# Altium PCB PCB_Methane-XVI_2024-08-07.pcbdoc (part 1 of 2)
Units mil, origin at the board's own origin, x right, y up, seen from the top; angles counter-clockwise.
Board outline 4553.3 x 5155.85 mil, 2 copper layers (Top Layer, Bottom Layer); 67 components, 58 nets, 315 pads, 114 vias.
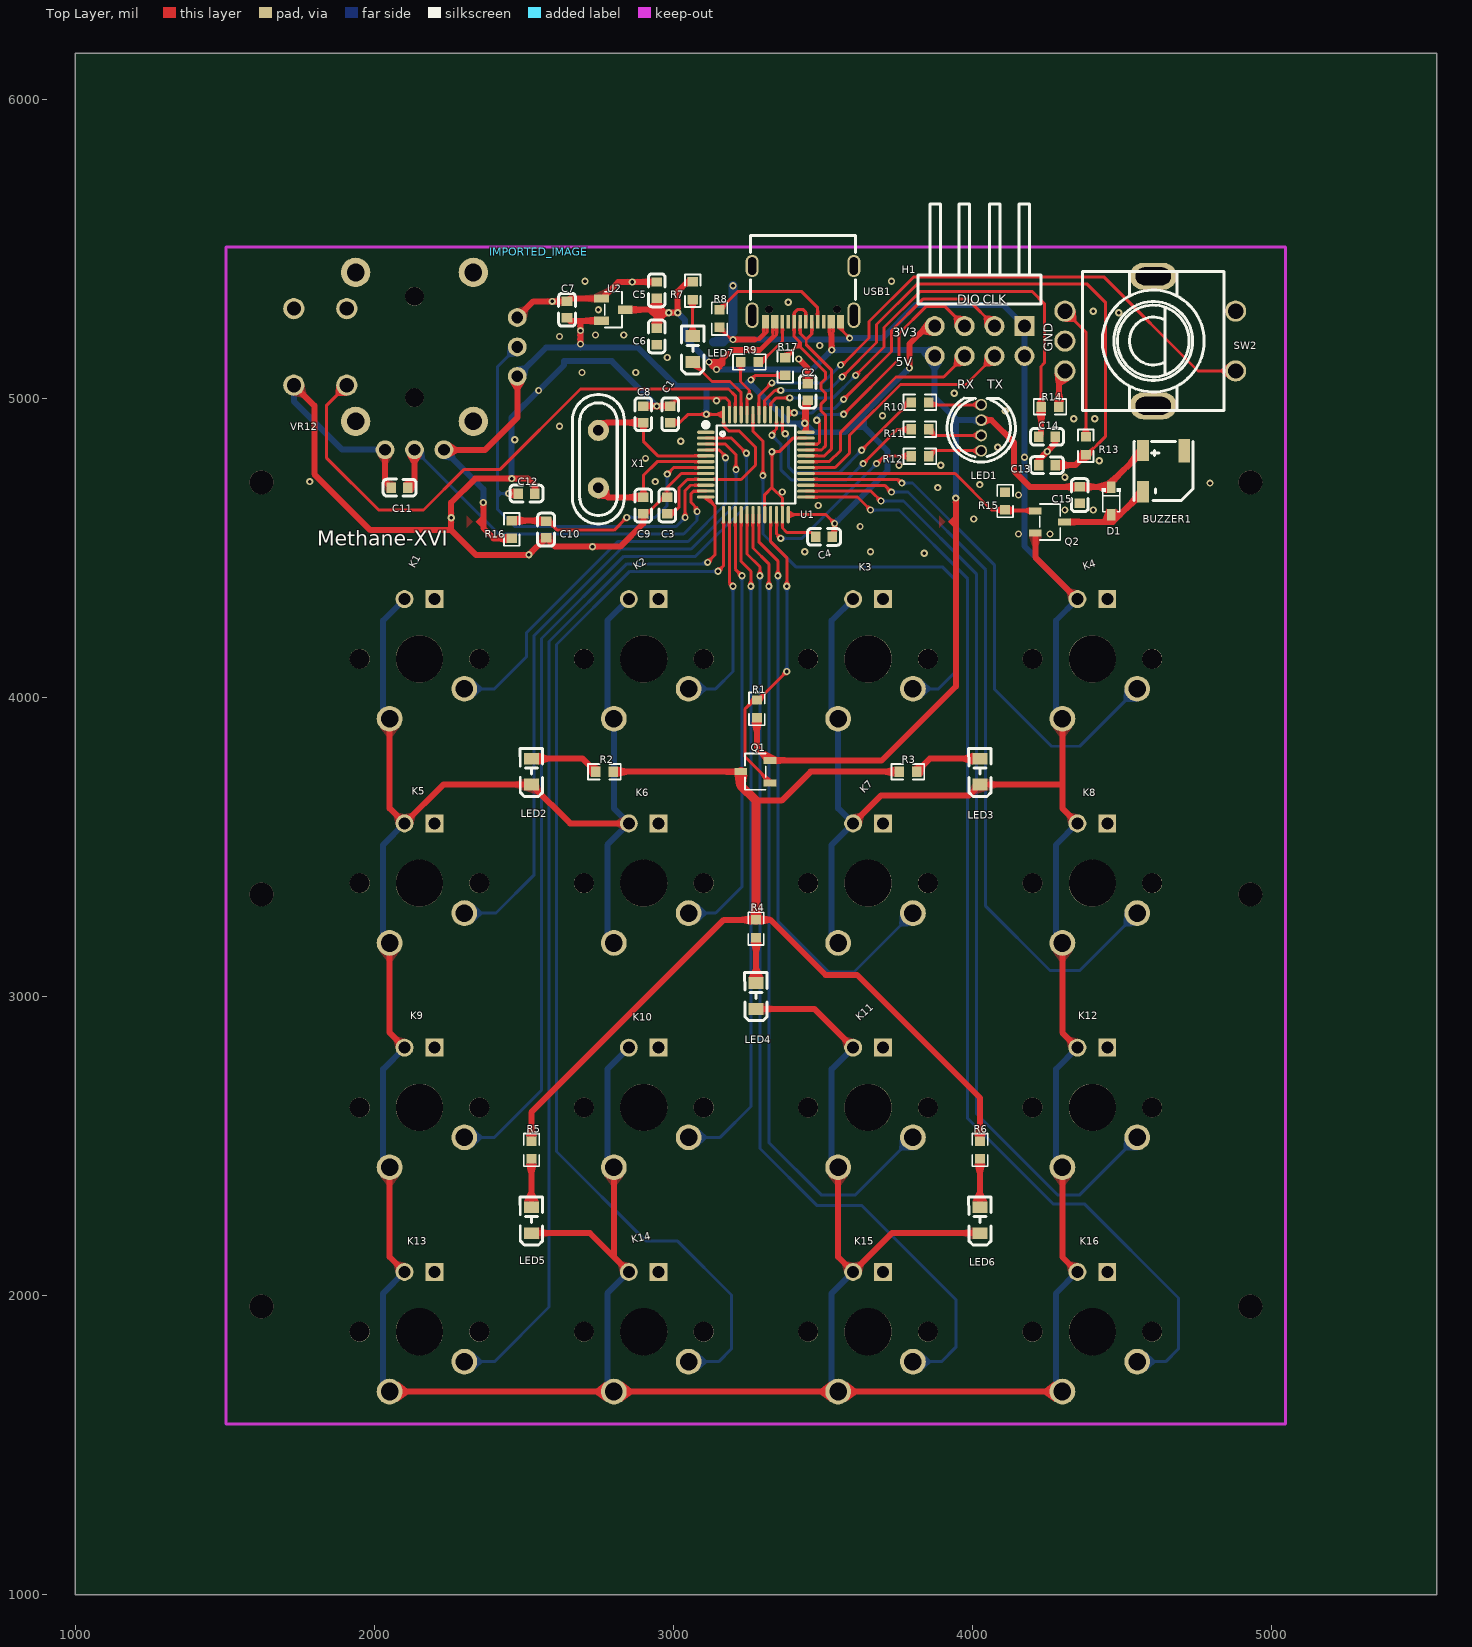
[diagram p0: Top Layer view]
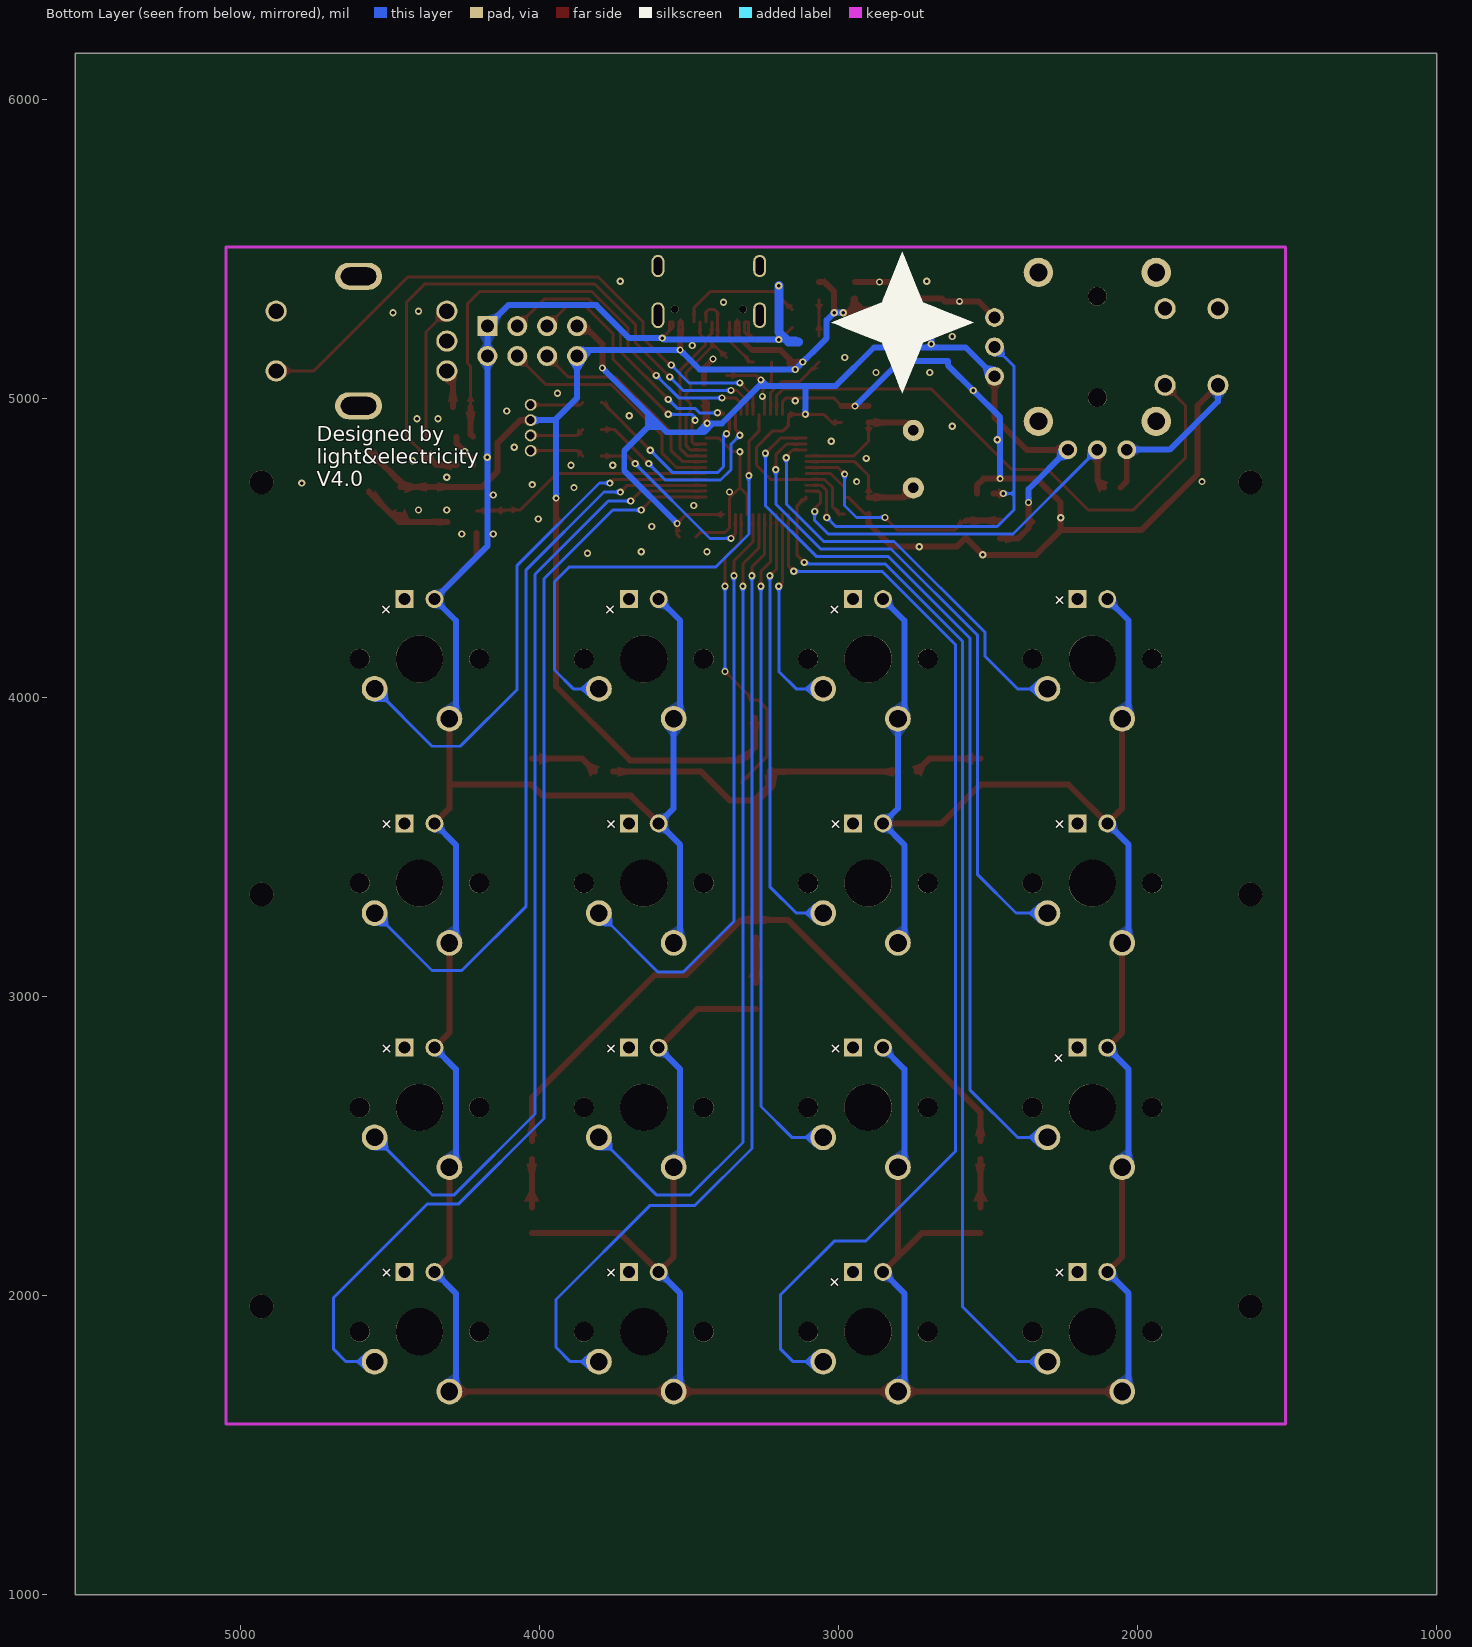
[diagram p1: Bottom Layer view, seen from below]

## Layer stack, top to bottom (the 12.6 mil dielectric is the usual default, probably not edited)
Top Layer: signal copper (thickness not stored)
Dielectric: dielectric 12.6, FR-4, Dk 4.8
Bottom Layer: signal copper (thickness not stored)

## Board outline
5553.3,1000 1000,1000 1000,6155.85 5553.3,6155.85

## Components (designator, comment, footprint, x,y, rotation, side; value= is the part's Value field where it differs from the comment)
BUZZER1 "FST-5020" BUZ-SMD_FST-5020 4640,4757.94 r270 top
C1 "0.1u" C0603 2990,4947.94 r270 top
C2 "0.1u" C0603 3450,5022.94 r270 top
C3 "0.1u" C0603 2980,4642.94 r270 top
C4 "0.1u" C0603 3505,4537.94 r0 top
C5 "0.1u" C0603 2945,5362.94 r90 top
C6 "1u" C0603 2945,5207.94 r270 top
C7 "1u" C0603 2645,5297.94 r90 top
C8 "22p" C0603 2900,4947.94 r270 top
C9 "22p" C0603 2900,4642.94 r90 top
C10 "0.1u" C0603 2575,4562.94 r90 top
C11 "1nF" C0603 2085,4702.94 r180 top
C12 "1nF" C0603 2510,4682.94 r0 top
C13 "0.1u" C0603 4250,4777.94 r0 top
C14 "0.1u" C0603 4250,4872.94 r180 top
C15 "0.1u" C0603 4360,4677.94 r90 top
D1 "B5819WS" SOD-323_L1.8-W1.3-LS2.5-RD 4465,4657.94 r270 top
H1 "PZ254-2-04-W-8.5" HDR-TH_8P-P2.54-H-M-R2-C4-S2.54-N 4024.68,5192.98 r180 top
IMPORTED_IMAGE "IMPORTED_IMAGE" IMPORTED_IMAGE 2550.47,5491.19 r0 top
K1 "NUM1" NEIL_MX_1U 2151.65,4130 r0 top
K2 "NUM2" NEIL_MX_1U 2901.65,4130 r0 top
K3 "NUM3" NEIL_MX_1U 3651.65,4130 r0 top
K4 "KEYA" NEIL_MX_1U 4401.65,4130 r0 top
K5 "NUM4" NEIL_MX_1U 2151.65,3380 r0 top
K6 "NUM5" NEIL_MX_1U 2901.65,3380 r0 top
K7 "NUM6" NEIL_MX_1U 3651.65,3380 r0 top
K8 "KEYB" NEIL_MX_1U 4401.65,3380 r0 top
K9 "NUM7" NEIL_MX_1U 2151.65,2630 r0 top
K10 "NUM8" NEIL_MX_1U 2901.65,2630 r0 top
K11 "NUM9" NEIL_MX_1U 3651.65,2630 r0 top
K12 "KEYC" NEIL_MX_1U 4401.65,2630 r0 top
K13 "KEY+" NEIL_MX_1U 2151.65,1880 r0 top
K14 "NUM0" NEIL_MX_1U 2901.65,1880 r0 top
K15 "KEY+" NEIL_MX_1U 3651.65,1880 r0 top
K16 "KEYD" NEIL_MX_1U 4401.65,1880 r0 top
LED1 "φ5 RGB Transparent" LED-TH_4P-BD5.8-P1.30 4030,4902.94 r90 top
LED2 "0805" LED0805-RD_GREEN 2526,3752.94 r90 top
LED3 "0805" LED0805-RD_GREEN 4026,3752.94 r90 top
LED4 "0805" LED0805-RD_GREEN 3277,3002.94 r90 top
LED5 "0805" LED0805-RD_GREEN 2526,2252.94 r90 top
LED6 "0805" LED0805-RD_GREEN 4026,2252.94 r90 top
LED7 "0805" LED0805-RD_GREEN 3065.39,5166.09 r90 top
Q1 "IRLML6401" SOT-23-3_L2.9-W1.6-P1.90-LS2.8-BR 3275.01,3752.94 r0 top
Q2 "AO3400" SOT-23-3_L2.9-W1.6-P1.90-LS2.8-BR 4260,4587.94 r180 top
R1 "10k" R0603 3280,3962.94 r90 top
R2 "220R" R0603 2770,3752.94 r0 top
R3 "220R" R0603 3785,3752.94 r180 top
R4 "220R" R0603 3277,3227.94 r90 top
R5 "220R" R0603 2526,2487.94 r90 top
R6 "220R" R0603 4026,2487.94 r90 top
R7 "1k" R0603 3065.4,5361.04 r90 top
R8 "5.1k" R0603 3155,5267.94 r270 top
R9 "5.1k" R0603 3255,5122.94 r0 top
R10 "220R" R0603 3825,4987.94 r0 top
R11 "220R" R0603 3825,4897.94 r0 top
R12 "220R" R0603 3825,4807.94 r0 top
R13 "3.3k" R0603 4380,4842.94 r90 top
R14 "3.3k" R0603 4260,4972.94 r180 top
R15 "10k" R0603 4110,4657.94 r270 top
R16 "10k" R0603 2460,4562.94 r270 top
R17 "1.5k" R0603 3375,5107.94 r270 top
SW2 "EC11" SW-TH_5PIN_EC11E15244G1 4595.51,5192.98 r270 top
U1 "STM32F103C6T6" LQFP-48_L7.0-W7.0-P0.50-LS9.0-BL 3276.7,4779.64 r270 top
U2 "662K." SOT-23-3_L2.9-W1.3-P1.90-LS2.4-BR 2800,5297.94 r180 top
USB1 "TYPEC-304YDSW-ACP16" USB-C-SMD_TYPEC-304YDSW-ACP16 3434.13,5350.46 r180 top
VR12 "RKJXV122400R" RKJXV122400R 2134.92,5173.3 r270 top
X1 "8MHz" HC-49S_L11.0-W4.4-P4.88 2750,4797.94 r270 top

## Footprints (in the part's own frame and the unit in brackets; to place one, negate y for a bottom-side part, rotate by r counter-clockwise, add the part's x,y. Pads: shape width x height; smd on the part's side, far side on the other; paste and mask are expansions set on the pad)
BUZ-SMD_FST-5020 [mm]
  rect 1.8x1 smd paste+0 mask+0.051: 1(-1.75,-1.75) 2(1.75,-1.75)
  rect 2x1 smd paste+0 mask+0.051: 3(-1.75,1.75)
  silkscreen extent -2.5,-2.5 2.5,2.5
C0603 [mm]
  rect 0.8x0.9 smd paste+0 mask+0.051: 1(-0.7,0) 2(0.7,0)
  silkscreen extent -1.41,-0.71 1.39,0.72
HC-49S_L11.0-W4.4-P4.88 [mm]
  round 1.8 hole 0.9 paste+0 mask+0.051: 1(-2.44,0) 2(2.44,0)
  silkscreen extent -5.5,-2.2 5.5,2.2
HDR-TH_8P-P2.54-H-M-R2-C4-S2.54-N [mm]
  rect 1.7x1.7 hole 1.1 paste+0 mask+0.05: 1(-3.81,-1.27)
  round 1.7 hole 1.1 paste+0 mask+0.05: 2(-3.81,1.27) 3(-1.27,-1.27) 4(-1.27,1.27) 5(1.27,-1.27) 6(1.27,1.27) 7(3.81,-1.27) 8(3.81,1.27)
  silkscreen extent -5.23,-11.63 5.23,-3.13
IMPORTED_IMAGE [mil]
LED0805-RD_GREEN [mm]
  rect 1x1.25 smd paste+0 mask+0.051: 1(-1.1,0) 2(1.1,0)
  silkscreen extent -2.1,-0.95 1.98,0.96
LED-TH_4P-BD5.8-P1.30 [mm]
  round 1 hole 0.7 paste+0 mask+0.051: 1(1.95,0) 2(0.65,0) 3(-0.65,0) 4(-1.95,0)
  silkscreen extent -2.91,-2.9 2.51,2.9
LQFP-48_L7.0-W7.0-P0.50-LS9.0-BL [mm]
  oval 0.27x1.5 smd paste+0 mask+0.05: 1(-2.75,-4.25) 2(-2.25,-4.25) 3(-1.75,-4.25) 4(-1.25,-4.25) 5(-0.75,-4.25) 6(-0.25,-4.25) 7(0.25,-4.25) 8(0.75,-4.25) 9(1.25,-4.25) 10(1.75,-4.25) 11(2.25,-4.25) 12(2.75,-4.25) 25(2.75,4.25) 26(2.25,4.25) 27(1.75,4.25) 28(1.25,4.25) 29(0.75,4.25) 30(0.25,4.25) 31(-0.25,4.25) 32(-0.75,4.25) 33(-1.25,4.25) 34(-1.75,4.25) 35(-2.25,4.25) 36(-2.75,4.25)
  oval 1.5x0.27 smd paste+0 mask+0.05: 13(4.25,-2.75) 14(4.25,-2.25) 15(4.25,-1.75) 16(4.25,-1.25) 17(4.25,-0.75) 18(4.25,-0.25) 19(4.25,0.25) 20(4.25,0.75) 21(4.25,1.25) 22(4.25,1.75) 23(4.25,2.25) 24(4.25,2.75) 37(-4.25,2.75) 38(-4.25,2.25) 39(-4.25,1.75) 40(-4.25,1.25) 41(-4.25,0.75) 42(-4.25,0.25) 43(-4.25,-0.25) 44(-4.25,-0.75) 45(-4.25,-1.25) 46(-4.25,-1.75) 47(-4.25,-2.25) 48(-4.25,-2.75)
  silkscreen extent -3.59,-4.46 3.3,3.34
NEIL_MX_1U [mil]
  round 86 hole 59 paste+0 mask+4: 1(-100,-200) 2(150,-100)
  rect 60x60 hole 40 paste+0 mask+4: +(50,200)
  round 60 hole 40 paste+0 mask+4: -(-50,200)
  round 66.93 hole 66.93 unplated paste+0: ""(-200,0) ""(200,0)
  round 157.48 hole 157.48 unplated paste+0: ""(0,0)
R0603 [mil]
  rect 31.75x34.02 smd paste-3937.01 mask+2: 1(-29.66,0) 2(29.65,0)
  silkscreen extent -55,-26 55,26
RKJXV122400R [mm]
  round 1.8 hole 1.2 paste+0 mask+0.051: a(-3.25,-5.75) b(-3.25,-10.25) c(3.25,-5.75) d(3.25,-10.25)
  round 1.6 hole 1 paste+0 mask+0.051: A1(2.5,8.73) A2(0,8.73) A3(-2.5,8.73) B1(8.73,-2.5) B2(8.73,0) B3(8.73,2.5)
  round 2.5 hole 1.5 paste+0 mask+0.051: S1(-6.325,5) S1(-6.325,-5) S1(6.325,5) S1(6.325,-5)
  round 1.6 hole 1.6 unplated paste+0: ""(-4.3,0) ""(4.3,0)
SOD-323_L1.8-W1.3-LS2.5-RD [mm]
  rect 1x0.75 smd paste+0 mask+0.051: 1(-1.173,0) 2(1.173,0)
  silkscreen extent -1.08,-0.8 0.9,0.8
SOT-23-3_L2.9-W1.3-P1.90-LS2.4-BR [mm]
  rect 1.25x0.7 smd paste+0 mask+0.051: 1(1,-0.95) 2(1,0.95) 3(-1,0)
  silkscreen extent -0.73,-1.53 0.73,1.53
SOT-23-3_L2.9-W1.6-P1.90-LS2.8-BR [mm]
  rect 1.07x0.6 smd paste+0 mask+0.051: 1(1.235,-0.95) 2(1.235,0.95) 3(-1.235,0)
  silkscreen extent -0.88,-1.54 0.88,1.54
SW-TH_5PIN_EC11E15244G1 [mm]
  oval 2.3x4 hole 1.5 slot 3 at 90 deg paste+0 mask+0.102: 6(5.5,0.25) 7(-5.5,0.25)
  round 1.8 hole 1.3 paste+0 mask+0.102: A(-2.54,-7.25) B(2.54,-7.25) C(0,-7.25) D(-2.54,7.25) E(2.54,7.25)
  silkscreen extent -5.9,-5.75 5.9,6.25
USB-C-SMD_TYPEC-304YDSW-ACP16 [mm]
  oval 1.1x2.2 hole 0.7 slot 1.8 at 90 deg paste+0 mask+0.051: 17(-4.32,1.808) 20(4.32,1.808)
  oval 1.1x1.9 hole 0.7 slot 1.5 at 90 deg paste+0 mask+0.051: 18(-4.32,-2.373) 19(4.32,-2.373)
  rect 0.3x1.15 smd paste-100 mask+0.051: A1(-3.35,2.373) A4(-2.55,2.373) A5(-1.25,2.373) A6(-0.25,2.373) A7(0.25,2.373) A8(1.25,2.373) A9(2.55,2.372) A12(3.35,2.373) B1(3.05,2.373) B4(2.25,2.372) B5(1.75,2.373) B6(0.75,2.373) B7(-0.75,2.373) B8(-1.75,2.373) B9(-2.25,2.373) B12(-3.05,2.373)
  round 0.65 hole 0.65 unplated paste+0: ""(-2.89,1.307) ""(2.89,1.308)
  silkscreen extent -4.47,-4.97 4.47,0.49

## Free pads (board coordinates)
  round 80 hole 80 unplated paste+0: ""(1623.11,1964.64) ""(1623.11,3342.59) ""(1623.11,4720.54) ""(4930.19,1964.64) ""(4930.19,3342.59) ""(4930.19,4720.54)

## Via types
v1: diameter 24.41, hole 12.2, Top Layer to Bottom Layer, tented both sides, 59 vias
v2: diameter 24, hole 12, Top Layer to Bottom Layer, tented both sides, 55 vias

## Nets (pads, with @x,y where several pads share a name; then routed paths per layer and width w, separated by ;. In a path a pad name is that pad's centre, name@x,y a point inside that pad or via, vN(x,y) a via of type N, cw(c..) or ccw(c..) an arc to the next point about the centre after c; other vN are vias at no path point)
3V3: C1.2 C2.2 C3.2 C4.2 C7.1 H1.7 R16.2 R17.2 U1.9 U1.24 U1.36 U1.48 U2.2 VR12.A1 VR12.B3 | length 5096.1
  Top Layer w10: C3.2@2980,4615.34 2997.4,4615.34 3020,4637.94 3020,4702.94 3047.4,4730.34 3109.3,4730.34 3227.4,4730.34 3275,4777.94 3275,4837.94 3220,4892.94 3185,4892.94 3168.4,4909.54 3168.4,4946.94 3168.4,4947.94 v2(3111.01,4947.94) 3050,4947.94 3022.4,4920.34 C1.2@2990,4920.34 ; v2(3260,5062.94) 3275.3,5078.24 R17.2@3375,5078.24 ; U1.24@3384.9,4612.24 3510.7,4612.24 v2(3540,4582.94) 3540,4545.34 C4.2@3532.55,4537.94 ; v2(3440,4917.94) 3444,4913.94 U1.36@3444,4887.84 ; U1.36@3444.02,4887.91 3450,4893.84 C2.2@3450,4995.34
  Top Layer w20: VR12.B3@2233.34,4829.59 2235,4827.94 2370,4827.94 2478.6,4936.54 VR12.A1@2478.6,5074.84 ; v2(2365,4652.94) 2365,4567.94 2399.7,4533.24 R16.2@2460,4533.24 ; C7.1@2645,5270.34 2654.8,5260.54 U2.2@2760.63,5260.54 ; v1(2690,5183.24) v1(2690,5227.94) 2690,5260.54 ; v2(3440,4917.94) 3440,4985.34 C2.2@3450,4995.34 ; v2(3790,5102.94) 3790,5182.94 3850.04,5242.98 H1.7@3874.68,5242.98
  Bottom Layer w20: VR12.B3@2233.34,4829.59 2365,4697.93 v2(2365,4652.94) ; VR12.A1@2478.6,5074.84 2575,5171.24 2881.7,5171.24 3010,5042.94 3265,5042.94 ; v1@2690,5171.24 v1(2690,5183.24) v1(2690,5227.94) ; v2(3111.01,4947.94) 3111.01,5042.94 ; 3197.15,5042.94 3240,5042.94 v2(3260,5062.94) 3260,5047.94 3265,5042.94 ; v2(3540,4582.94) 3716.9,4759.84 3716.9,4826.04 3615,4927.94 ; 3637,4949.94 3637.8,4905.14 ; 3637.35,4905.59 3592.65,4905.59 3575,4887.94 ; v2(3790,5102.94) 3575,4887.94 ; 3265,5042.94 3390,4917.94 ; 3390,4917.94 3420,4917.94 3450,4887.94 3470,4887.94 ; 3390,4917.94 v2(3440,4917.94) 3470,4887.94 ; 3470,4887.94 3575,4887.94
+5V: BUZZER1.1 C5.1 C6.1 C15.2 D1.1 H1.8 LED1.2 Q1.2 R1.1 R7.2 U2.3 USB1.A4 USB1.A9 USB1.B4 USB1.B9 | length 5330.8
  Top Layer w10: 3245.2,5158.14 3290.2,5158.14 3345.6,5213.44 3345.6,5257.04 3333.7,5257.04 3333.7,5211.64 3285,5162.94 3250,5162.94 ; 3522.7,5220.24 3522.7,5257.04 3534.5,5257.04 3534.5,5222.44 3527.5,5215.44 3522.7,5220.24
  Top Layer w20: U2.3@2839.37,5297.94 2938.2,5297.94 2950,5309.74 ; 2917.67,5297.94 2921.96,5297.94 2950,5269.9 ; 2922,5297.94 2945,5320.94 C5.1@2945,5335.34 ; C6.1@2950,5233.04 C5.1@2950,5332.94 ; 2950,5262.74 2975.2,5287.94 v1(2985,5287.94) ; 2950,5309.78 2971.84,5287.94 v1(2985,5287.94) ; R7.2@3065.4,5390.69 3047.8,5390.74 3015,5357.94 v1(3015,5287.94) v1(2985,5287.94) ; 3145,5112.94 3135,5122.94 v1(3120,5122.94) ; R1.1@3280,3933.24 3280,3833.94 Q1.2@3323.62,3790.34 3697.4,3790.34 3945,4037.94 v2(3945,4667.94) ; 3285,5162.94 3195,5162.94 3165,5132.94 ; 3527.5,5215.44 3530,5215.44 v2(3530,5162.94) ; LED1.2@4030,4928.53 4064.4,4928.54 4140,4852.94 4140,4757.94 4192.4,4705.54 C15.2@4360,4705.49 ; D1.1@4465,4704.1 4463.6,4705.54 C15.2@4360,4705.49 ; BUZZER1.1@4571.1,4826.84 4449.8,4705.54 C15.2@4360,4705.49 ; v1(3120,5122.94) v2(3145,5097.94) 3165,5117.94 3165,5132.94 ; v1(3120,5122.94) 3155,5122.94 3165,5132.94
  Bottom Layer w20: v1(2985,5287.94) v1(3015,5287.94) 3040.3,5262.64 3040.3,5202.64 v2(3145,5097.94) 3465,5097.94 v2(3530,5162.94) 3874.7,5162.94 H1.8@3874.7,5142.94 ; H1.8@3874.68,5142.98 3874.68,5003.26 3949.41,4928.53 ; v2(3945,4667.94) 3945,4924.12 3949.41,4928.53 ; LED1.2@4030,4928.53 3949.41,4928.53
ANA1: C11.1 U1.11 VR12.B2 | length 1367.3
  Top Layer w10: v2(3080,4622.94) 3080,4632.94 3060,4652.94 3060,4682.94 3068.1,4691.04 U1.11@3109.3,4691.04
  Top Layer w20: C11.1@2112.55,4702.94 2134.9,4725.34 VR12.B2@2134.92,4829.59
  Bottom Layer w10: VR12.B2@2134.92,4829.59 2416.6,4547.94 3035,4547.94 3080,4592.94 v2(3080,4622.94)
ANA2: C12.1 U1.10 VR12.A2 | length 1497.3
  Top Layer w10: v2(3040,4602.94) 3040,4692.94 3057.8,4710.74 U1.10@3109.3,4710.74
  Top Layer w20: v1(2450,4682.94) C12.1@2482.45,4682.94
  Bottom Layer w10: 2413.1,4672.94 2423.1,4682.94 ; 2413.1,4702.57 2413.1,4692.94 2423.1,4682.94 ; v1(2450,4682.94) 2423.1,4682.94 ; VR12.A2@2478.6,5173.24 2413.1,5107.74 2413.1,4629.84 2470,4572.94 3010,4572.94 v2(3040,4602.94)
BUZZ: Q2.1 R15.2 U1.29 | length 894.2
  Top Layer w10: U1.29@3444,4750.04 3942.9,4750.04 4064.7,4628.24 R15.2@4110,4628.24 ; R15.2@4114.7,4627.94 4194.7,4627.94 Q2.1@4197.3,4625.34 ; R15.2@4117.3,4625.34 Q2.1@4211.38,4625.34
BUZZER1_2: BUZZER1.2 D1.2 Q2.3 | length 608.8
  Top Layer w20: Q2.3@4308.63,4587.94 4441.2,4587.94 4465,4611.74 4493.8,4611.74 BUZZER1.2@4571.1,4689.04 4470,4587.94 Q2.3@4308.63,4587.94
EC1: C13.2 R13.1 U1.41 | length 2063.8
  Top Layer w10: U1.41@3306.2,4946.94 3306.2,4994.14 3340,5027.94 v2(3360,5027.94) ; v2(3565,5072.94) 3680,5187.94 3680,5247.94 3815,5382.94 4385,5382.94 4445,5322.94 4445,4872.94 4385.3,4813.24 R13.1@4380,4813.24
  Top Layer w20: C13.2@4277.56,4777.94 4344.7,4777.94 R13.1@4380,4813.24
  Bottom Layer w10: v2(3360,5027.94) 3520,5027.94 v2(3565,5072.94)
EC2: C14.2 R14.2 U1.40 | length 1614.7
  Top Layer w10: U1.40@3325.9,4946.94 3325.9,4983.84 3345,5002.94 v2(3390,5002.94) ; v2(3610,5077.94) 3705,5172.94 3705,5237.94 3825,5357.94 4201.3,5357.94 4241.3,5317.94 4241.3,5119.24 4230.3,5108.24 R14.2@4230.35,4972.94
  Top Layer w20: C14.2@4222.44,4872.94 4230.3,4880.84 R14.2@4230.35,4972.94
  Bottom Layer w10: v2(3390,5002.94) 3535,5002.94 v2(3610,5077.94)
GATE: Q1.1 R1.2 U1.21 | length 1020.5
  Top Layer w10: Q1.1@3323.62,3715.54 3323.6,3719.34 3240,3802.94 3240,3962.94 3269.7,3992.64 R1.2@3280,3992.59 3284.7,3992.64 v2(3380,4087.94) ; U1.21@3325.9,4612.24 3325.9,4522.04 3380,4467.94 v2(3380,4372.94)
  Bottom Layer w10: v2(3380,4087.94) v2(3380,4372.94)
GND: C1.1 C2.1 C3.1 C4.1 C5.2 C6.2 C7.2 C8.1 C9.1 C10.1 C11.2 C12.2 C13.1 C14.1 C15.1 H1.1 H1.2 K1.1 K1.- K2.1 K2.- K3.1 K3.- K4.1 K4.- K5.1 K5.- K6.1 K6.- K7.1 K7.- K8.1 K8.- K9.1 K9.- K10.1 K10.- K11.1 K11.- K12.1 K12.- K13.1 K13.- K14.1 K14.- K15.1 K15.- K16.1 K16.- LED2.1 LED3.1 LED4.1 LED5.1 LED6.1 Q2.2 R8.2 R9.1 R15.1 SW2.C SW2.D U1.8 U1.20 U1.23 U1.35 U1.44 U1.47 U2.1 USB1.A1 USB1.A12 USB1.B1 USB1.B12 VR12.A3 VR12.B1 VR12.d | length 24692.8
  Top Layer w10: C9.1@2900,4615.34 2912.4,4615.34 2967.6,4670.54 C3.1@2980,4670.49 2980,4702.94 3027.1,4750.04 U1.8@3109.3,4750.04 ; C1.1@2990,4975.49 3017.4,5002.94 3175,5002.94 3188.1,4989.84 U1.47@3188.1,4946.94 ; R8.2@3155,5238.24 3195.3,5197.94 v2(3200,5197.94) ; R9.1@3225.34,5122.94 3225.3,5057.64 3255,5027.94 v2(3255,5007.94) 3247.1,5000.04 U1.44@3247.1,4946.94 ; U1.20@3306.2,4612.24 3306.2,4679.14 3330,4702.94 v2(3330,4822.94) 3355,4822.94 3400.2,4868.14 U1.35@3444,4868.14 ; 3335,4697.94 3365.2,4667.74 3365.2,4612.24 3365.2,4567.74 3380,4552.94 3462.4,4552.94 C4.1@3477.45,4537.94 ; v2(3200,5197.94) 3289.9,5197.94 3314,5222.04 3314,5257.04 3302.2,5257.04 3302.2,5220.14 3280,5197.94 v2(3200,5197.94) ; USB1.B12@3554.2,5238.74 3554.2,5257.04 3566,5257.04 3566,5226.94 v2(3590,5202.94) USB1.B12@3554.2,5238.74
  Top Layer w20: VR12.d@1731.38,5045.34 1800,4976.74 1800,4747.94 1987.6,4560.34 2257.6,4560.34 ; VR12.B1@2036.49,4829.59 2036.5,4723.84 C11.2@2057.45,4702.94 ; K13.1@2051.65,1680 K14.1@2801.65,1680 K15.1@3551.65,1680 K16.1@4301.65,1680 ; K9.1@2051.65,2430 2051.65,2130 K13.-@2101.65,2080 ; K5.1@2051.65,3180 2051.65,2880 K9.-@2101.65,2830 ; K1.1@2051.65,3930 2051.65,3630 K5.-@2101.65,3580 ; K5.-@2101.7,3580.04 2231.3,3709.64 LED2.1@2526,3709.63 2655.6,3580.04 K6.-@2851.7,3580.04 ; VR12.A3@2478.62,5271.72 2532.4,5325.54 v1(2595.72,5325.54) C7.2@2645,5325.49 2654.8,5335.34 U2.1@2760.63,5335.34 2815.8,5390.54 v1(2863.43,5390.54) C5.2@2945,5390.49 ; LED5.1@2526,2209.63 2722,2209.64 K14.-@2851.7,2080.04 ; C12.2@2537.55,4682.94 2537.6,4710.34 2515,4732.94 v2(2460,4732.94) 2337.6,4732.94 2257.6,4652.94 v1(2257.6,4602.24) 2257.6,4560.34 ; K10.1@2801.65,2430 2801.65,2130 K14.-@2851.65,2080 ; C9.1@2900,4615.34 2900,4582.94 2822.4,4505.34 v1(2730.39,4505.34) 2605,4505.34 2575,4535.34 v1(2517.6,4477.94) 2340,4477.94 2257.6,4560.34 ; C8.1@2900,4975.49 v2(2945.2,4975.5) C1.1@2990,4975.49 ; v2(3200,5197.94) 3272.44,5197.94 3270,5197.94 ; LED4.1@3277,2959.63 3472,2959.64 K11.-@3601.7,2830.04 ; v1(3420,5132.94) 3450,5102.94 C2.1@3450,5050.49 ; K11.1@3551.65,2430 3551.65,2130 K15.-@3601.65,2080 ; K15.-@3601.7,2080.04 3731.3,2209.64 LED6.1@4026,2209.63 ; K7.-@3601.7,3580.04 3694.6,3672.94 3989.3,3672.94 LED3.1@4026,3709.63 4301.7,3709.64 ; Q2.2@4211.38,4550.54 4211.4,4470.34 K4.-@4351.7,4330.04 ; C13.1@4222.44,4777.94 4222.4,4795.34 v1(4250.49,4823.43) 4277.6,4850.54 C14.1@4277.56,4872.94 ; K12.1@4301.65,2430 4301.65,2130 K16.-@4351.65,2080 ; K8.1@4301.65,3180 4301.65,2880 K12.-@4351.65,2830 ; K4.1@4301.65,3930 4301.65,3630 K8.-@4351.65,3580
  Bottom Layer w20: VR12.d@1731.38,5045.34 1731.4,4991.54 1893.3,4829.64 VR12.B1@2036.49,4829.59 ; K13.1@2051.65,1680 2030,1701.65 2030,2008.35 K13.-@2101.65,2080 ; K9.1@2051.65,2430 2030,2451.65 2030,2758.35 K9.-@2101.65,2830 ; K5.1@2051.65,3180 2030,3201.65 2030,3508.35 K5.-@2101.65,3580 ; K1.1@2051.65,3930 2030,3951.65 2030,4258.35 K1.-@2101.65,4330 ; v2(2460,4732.94) 2460,4937.58 v2(2550,5027.58) ; v2@2550,5027.54 2635,5112.54 2635,5125.74 2795,5125.74 v2(2945.2,4975.5) ; K14.1@2801.65,1680 2780,1701.65 2780,2008.35 K14.-@2851.65,2080 ; K10.1@2801.65,2430 2780,2451.65 2780,2758.35 K10.-@2851.65,2830 ; K6.1@2801.65,3180 2780,3201.65 2780,3508.35 K6.-@2851.65,3580 2801.65,3630 K2.1@2801.65,3930 2780,3951.65 2780,4258.35 K2.-@2851.65,4330 ; 3135,5190.34 3142.6,5197.94 v2(3200,5197.94) 3585,5197.94 v2(3590,5202.94) 3700,5202.94 3810,5312.94 4104.7,5312.94 4174.7,5242.94 H1.2@4174.7,5142.94 ; K15.1@3551.65,1680 3530,1701.65 3530,2008.35 K15.-@3601.65,2080 ; K7.1@3551.65,3180 3530,3201.65 3530,3508.35 K7.-@3601.65,3580 3551.65,3630 K3.1@3551.65,3930 3530,3951.65 3530,4258.35 K3.-@3601.65,4330 ; K11.1@3551.7,2430.04 3530,2451.64 3530,2758.34 K11.-@3601.7,2830.04 ; H1.2@4174.68,5142.98 v1(4174.68,4804.13) 4174.68,4790.65 4174.68,4506.97 K4.-@4351.65,4330 4280,4258.35 4280,3951.65 K4.1@4301.65,3930 ; K16.1@4301.65,1680 4280,1701.65 4280,2008.35 K16.-@4351.65,2080 ; K12.1@4301.65,2430 4280,2451.65 4280,2758.35 K12.-@4351.65,2830 ; K8.1@4301.65,3180 4280,3201.65 4280,3508.35 K8.-@4351.65,3580
  Bottom Layer w30: 3135,5190.34 3167.4,5190.34 3200,5222.94 v2(3200,5377.94)
  other v1: 3840,4482.94 3440,4487.94 3660,4487.94 4155,4547.94 4260,4547.94 3625,4572.94 4005,4597.94 4310,4627.94 4405,4627.94 3485,4642.94 4155,4677.94 3365,4687.94 3885,4702.94 4025,4712.94 4795,4717.94 1785,4722.94 2940,4722.94 4310,4737.94 3755,4777.94 3895,4777.94 4425,4792.94 2907.5,4800.44 4085,4837.94 3025,4857.94 2470,4862.94 2620,4907.94 4340,4932.94 4410,4932.94 3700,4942.94 4110.22,4958.8 3145,4992.94 3940,5017.94 2695,5087.94 2875,5087.94 2980,5137.94 3490,5177.94 2620,5207.94 2740,5212.94 2835,5212.94 4490,5287.94 4405,5292.94 2750,5297.94 3385,5322.94 2705,5392.94 3730,5392.94
KEY1: K1.2 U1.4 | length 1410.5
  Top Layer w10: U1.4@3109.3,4828.84 3154.1,4828.84 3175,4807.94 v2(3175,4802.94)
  Bottom Layer w10: K1.2@2301.7,4030.04 2402.1,4030.04 2510,4137.94 2510,4217.94 2815,4522.94 3050,4522.94 3175,4647.94 v2(3175,4802.94)
KEY2: K2.2 U1.14 | length 701.5
  Top Layer w10: U1.14@3188.1,4612.24 3188.1,4384.84 v2(3200,4372.94)
  Bottom Layer w10: K2.2@3051.7,4030.04 3142.1,4030.04 3200,4087.94 v2(3200,4372.94)
KEY3: K3.2 U1.43 | length 1598.4
  Top Layer w10: U1.43@3266.8,4946.94 3266.8,4891.14 3300,4857.94 v2(3300,4742.94)
  Bottom Layer w10: v2(3300,4742.94) 3300,4547.94 3410,4437.94 3900,4437.94 3950,4387.94 3950,4092.94 3887.1,4030.04 K3.2@3801.7,4030.04
KEY4: K4.2 U1.28 | length 1799.9
  Top Layer w10: U1.28@3444,4730.34 3752.6,4730.34 v2(3765,4717.94)
  Bottom Layer w10: v2(3765,4717.94) 3800,4717.94 4075,4442.94 4075,4027.94 4265,3837.94 4359.59,3837.94 K4.2@4551.65,4030
KEY5: K5.2 U1.3 | length 2223.9
  Top Layer w10: U1.3@3109.3,4848.44 3174.5,4848.44 3210,4812.94 v2(3210,4762.94)
  Bottom Layer w10: K5.2@2301.7,3280.04 2407.1,3280.04 2535,3407.94 2535,4207.94 2825,4497.94 3060,4497.94 3210,4647.94 v2(3210,4762.94)
KEY6: K6.2 U1.15 | length 1468.2
  Top Layer w10: U1.15@3207.7,4612.24 3207.7,4430.24 v2(3230,4407.94)
  Bottom Layer w10: K6.2@3051.7,3280.04 3142.1,3280.04 3230,3367.94 v2(3230,4407.94)
KEY7: K7.2 U1.19 | length 1989.3
  Top Layer w10: U1.19@3286.5,4612.24 3286.5,4521.44 3350,4457.94 v2(3350,4407.94)
  Bottom Layer w10: v2(3350,4407.94) 3350,3252.94 3520,3082.94 3604.59,3082.94 K7.2@3801.65,3280
KEY8: K8.2 U1.27 | length 2518.4
  Top Layer w10: U1.27@3444,4710.64 3707.3,4710.64 v2(3730,4687.94)
  Bottom Layer w10: v2(3730,4687.94) 3785,4687.94 4045,4427.94 4045,3302.94 4260,3087.94 4359.59,3087.94 K8.2@4551.65,3280
KEY9: K9.2 U1.2 | length 3034.5
  Top Layer w10: U1.2@3109.3,4868.14 3194.8,4868.14 v2(3245,4817.94)
  Bottom Layer w10: K9.2@2301.7,2530.04 2402.1,2530.04 2560,2687.94 2560,4197.94 2835,4472.94 3075,4472.94 3245,4642.94 v2(3245,4817.94)
KEY10: K10.2 U1.16 | length 2243.8
  Top Layer w10: U1.16@3227.4,4612.24 3227.4,4455.54 3260,4422.94 v2(3260,4372.94)
  Bottom Layer w10: K10.2@3051.65,2530 3157.06,2530 3260,2632.94 v2(3260,4372.94)
KEY11: K11.2 U1.18 | length 2755
  Top Layer w10: U1.18@3266.8,4612.24 3266.8,4501.14 3320,4447.94 v2(3320,4372.94)
  Bottom Layer w10: v2(3320,4372.94) 3320,2512.94 3495,2337.94 3609.59,2337.94 K11.2@3801.65,2530
KEY12: K12.2 U1.26 | length 3219.2
  Top Layer w10: U1.26@3444,4691.04 3661.9,4691.04 v2(3695,4657.94)
  Bottom Layer w10: v2(3695,4657.94) 3770,4657.94 4015,4412.94 4015,2607.94 4285,2337.94 4359.59,2337.94 K12.2@4551.65,2530
KEY13: K13.2 U1.12 | length 3468.2
  Top Layer w10: U1.12@3109.3,4671.34 3140,4640.64 3140,4477.94 v2(3115,4452.94)
  Bottom Layer w10: K13.2@2301.7,1780.04 2402.1,1780.04 2585,1962.94 2585,4187.94 2845,4447.94 3115,4447.94 v2(3115,4452.94)
KEY14: K14.2 U1.13 | length 3658.3
  Top Layer w10: v2(3150,4422.94) 3168.4,4441.34 U1.13@3168.4,4612.24
  Bottom Layer w10: K14.2@3051.7,1780.04 3152.1,1780.04 3195,1822.94 3195,2002.94 3015,2182.94 2910,2182.94 2610,2482.94 2610,4177.94 2855,4422.94 v2(3150,4422.94)
KEY15: K15.2 U1.17 | length 3324.4
  Top Layer w10: U1.17@3247.1,4612.24 3247.1,4480.84 3290,4437.94 v2(3290,4407.94)
  Bottom Layer w10: v2(3290,4407.94) 3290,2492.94 3480,2302.94 3630,2302.94 3945,1987.94 3945,1827.94 3897.1,1780.04 K15.2@3801.7,1780.04
KEY16: K16.2 U1.25 | length 3738.8
  Top Layer w10: U1.25@3444,4671.34 3616.6,4671.34 v2(3660,4627.94)
  Bottom Layer w10: v2(3660,4627.94) 3755,4627.94 3985,4397.94 3985,2592.94 4270,2307.94 4375,2307.94 4690,1992.94 4690,1822.94 4647.1,1780.04 K16.2@4551.7,1780.04
KEY17: U1.46 VR12.c | length 1951.4
  Top Layer w10: VR12.c@1908.54,5045.34 1840,4976.84 1840,4802.94 2015,4627.94 2165,4627.94 2300,4762.94 2420,4762.94 2690,5032.94 3185,5032.94 3207.7,5010.24 U1.46@3207.7,4946.94
KEY18: SW2.E U1.42 | length 1984.7
  Top Layer w10: U1.42@3286.5,4946.94 3286.5,5009.44 v2(3330,5052.94) ; v2(3560,5112.94) 3565,5112.94 3655,5202.94 3655,5257.94 3805,5407.94 4440,5407.94 4755,5092.94 SW2.E@4880.9,5092.94
  Bottom Layer w10: v2(3330,5052.94) 3500,5052.94 v2(3560,5112.94)
LED: LED7.1 U1.45 | length 277.9
  Top Layer w10: LED7.1@3065.4,5122.74 3130.2,5057.94 3190,5057.94 3227.4,5020.54 U1.45@3227.4,4946.94
LED1_1: LED1.1 R10.2 | length 178.7
  Top Layer w10: R10.2@3854.66,4987.94 3862.9,4979.74 LED1.1@4030,4979.71
LED1_3: LED1.3 R11.2 | length 183.9
  Top Layer w10: R11.2@3854.66,4897.94 3875.2,4877.34 LED1.3@4030,4877.34
LED1_4: LED1.4 R12.2 | length 182.8
  Top Layer w10: R12.2@3854.66,4807.94 3872.9,4826.14 LED1.4@4030,4826.14
LED2_2: LED2.2 R2.1 | length 232.2
  Top Layer w20: LED2.2@2526,3796.24 2697,3796.24 R2.1@2740.34,3752.94
LED3_2: LED3.2 R3.1 | length 229.2
  Top Layer w20: R3.1@3814.66,3752.94 3858,3796.24 LED3.2@4026,3796.24
LED4_2: LED4.2 R4.1 | length 152
  Top Layer w20: LED4.2@3277,3046.24 R4.1@3277,3198.24
LED5_2: LED5.2 R5.1 | length 162
  Top Layer w20: LED5.2@2526,2296.24 R5.1@2526,2458.24
LED6_2: LED6.2 R6.1 | length 162
  Top Layer w20: LED6.2@4026,2296.24 R6.1@4026,2458.24
LED7_2: LED7.2 R7.1 | length 122
  Top Layer w10: LED7.2@3065.4,5209.34 R7.1@3065.4,5331.34
LEDB: R12.1 U1.22 | length 634.5
  Top Layer w10: U1.22@3345.6,4612.24 3345.6,4547.34 v2(3360,4532.94) ; v2(3680,4782.94) 3705,4807.94 R12.1@3795.34,4807.94
  Bottom Layer w10: v2(3360,4532.94) 3430,4532.94 v2(3680,4782.94)
LEDG: R11.1 U1.39 | length 723.1
  Top Layer w10: v2(3330,4877.94) 3330,4882.94 3345.6,4898.54 U1.39@3345.6,4946.94 ; v2(3635,4782.94) 3750,4897.94 R11.1@3795.34,4897.94
  Bottom Layer w10: v2(3330,4877.94) 3360,4847.94 3360,4762.94 3395,4727.94 3580,4727.94 v2(3635,4782.94)
LEDR: R10.1 U1.38 | length 698.1
  Top Layer w10: U1.38@3365.2,4946.94 3365.2,4892.74 v2(3375,4882.94) ; v2(3630,4827.94) 3790,4987.94 R10.1@3795.34,4987.94
  Bottom Layer w10: v2(3375,4882.94) 3385,4872.94 3385,4772.94 3405,4752.94 3555,4752.94 v2(3630,4827.94)
OSCIN: C8.2 U1.5 X1.1 | length 452.8
  Top Layer w10: C8.2@2900,4920.34 2900,4857.94 2948.8,4809.14 U1.5@3109.3,4809.14
  Top Layer w20: X1.1@2750,4894 2776.4,4920.34 C8.2@2900,4920.34
OSCOUT: C9.2 U1.6 X1.2 | length 463.9
  Top Layer w10: C9.2@2900,4670.49 2900,4742.94 2946.5,4789.44 U1.6@3109.3,4789.44
  Top Layer w20: X1.2@2750,4701.84 2781.4,4670.54 C9.2@2900,4670.49
R2_2: Q1.3 R2.2 R3.2 R4.2 R5.2 R6.2 | length 3715.4
  Top Layer w20: R5.2@2526,2517.59 2526,2613.94 3169.7,3257.64 R4.2@3277,3257.59 3325.3,3257.64 3510,3072.94 3615,3072.94 4026,2661.94 R6.2@4026,2517.59 ; R2.2@2799.66,3752.94 Q1.3@3226.38,3752.94 ; 3277,3655.94 3363,3655.94 3460,3752.94 R3.2@3755.34,3752.94
  Top Layer w30: Q1.3@3226.38,3752.94 3226.4,3706.54 3277,3655.94 R4.2@3277,3257.59
RX: H1.6 U1.31 | length 712.8
  Top Layer w10: U1.31@3444,4789.44 3521.5,4789.44 3560,4826.14 3560,4887.94 3745,5072.94 3904.6,5072.94 H1.6@3974.7,5142.94
S$40: 
S$120: 
S$53996: 
SW2_A: R13.2 SW2.A | length 449.3
  Top Layer w10: SW2.A@4310.1,5292.94 4380,5223.04 R13.2@4380,4872.6
SW2_B: R14.1 SW2.B | length 128.4
  Top Layer w20: R14.1@4289.65,4972.94 4289.7,5072.54 SW2.B@4310.1,5092.94
SWCLK: H1.3 U1.37 | length 931.5
  Top Layer w10: U1.37@3384.9,4946.94 3384.9,4952.94 v2(3405,4952.94) ; v2(3570,4997.94) 3730,5157.94 3730,5227.94 3835,5332.94 3984.7,5332.94 H1.3@4074.7,5242.94
  Bottom Layer w10: v2(3405,4952.94) 3465,4952.94 3480,4967.94 3540,4967.94 v2(3570,4997.94)
SWDIO: H1.5 U1.34 | length 860.2
  Top Layer w10: U1.34@3444.02,4848.54 3483.1,4848.54 3490,4855.44 3490,4917.94 v2(3480,4927.94) ; v2(3570,4947.94) 3755,5132.94 3755,5217.94 3845,5307.94 3909.7,5307.94 H1.5@3974.7,5242.94
  Bottom Layer w10: v2(3480,4927.94) 3480,4937.94 3490,4947.94 v2(3570,4947.94)
TX: H1.4 U1.30 | length 820.4
  Top Layer w10: U1.30@3444,4769.74 3541.8,4769.74 3590,4817.94 3590,4877.94 3760,5047.94 3979.6,5047.94 H1.4@4074.7,5142.94
U1_7: C10.2 R16.1 U1.7 | length 810.8
  Top Layer w10: C10.2@2575,4590.49 2582.4,4590.54 2612.4,4560.54 2802.6,4560.54 v2(2845,4602.94) ; v2(2980,4747.94) 3001.8,4769.74 U1.7@3109.3,4769.74
  Top Layer w20: R16.1@2460,4592.6 2572.9,4592.64 C10.2@2575,4590.49
  Bottom Layer w10: v2(2845,4602.94) 2940,4602.94 2980,4642.94 v2(2980,4747.94)
USB1_A5: R8.1 USB1.A5 | length 423
  Top Layer w10: R8.1@3155,5297.6 3215.3,5357.94 3430,5357.94 3483.3,5304.64 USB1.A5@3483.3,5257.04
USB1_B5: R9.2 USB1.B5 | length 173.5
  Top Layer w10: R9.2@3284.66,5122.94 3295,5122.94 3365.2,5193.14 USB1.B5@3365.2,5257.04
USBDM: U1.32 USB1.A7 USB1.B7 | length 630.6
  Top Layer w10: USB1.A7@3424.3,5257.04 3424.3,5218.64 3445,5197.94 ; U1.32@3444,4809.14 3506.2,4809.14 3530,4832.94 3530,5095.44 3445,5180.44 3445,5197.94 ; USB1.B7@3463.7,5257.04 3463.7,5216.64 3445,5197.94
USBDP: R17.1 U1.33 USB1.A6 USB1.B6 | length 759.3
  Top Layer w10: R17.1@3375,5137.6 3425,5187.94 ; 3403.64,5166.45 3410.13,5172.94 3425,5172.94 ; U1.33@3444.02,4828.85 3495.9,4828.84 3510,4842.94 3510,4943.94 3495,4958.94 3495,4982.94 3510,4997.94 3510,5017.94 3495,5032.94 3495,5052.94 3510,5067.94 3510,5087.94 3425,5172.94 ; USB1.A6@3444,5257.04 3444,5288.94 3435,5297.94 3415,5297.94 3404.6,5287.54 3404.6,5257.04 3404.6,5208.34 3425,5187.94 ; 3425,5172.94 3425,5187.94
pads on no net: BUZZER1.3 K1. K1.+ K2. K2.+ K3. K3.+ K4. K4.+ K5. K5.+ K6. K6.+ K7. K7.+ K8. K8.+ K9. K9.+ K10. K10.+ K11. K11.+ K12. K12.+ K13. K13.+ K14. K14.+ K15. K15.+ K16. K16.+ SW2.6 SW2.7 U1.1 USB1. USB1.17 USB1.18 USB1.19 USB1.20 USB1.A8 USB1.B8 VR12. VR12.a VR12.b VR12.S1

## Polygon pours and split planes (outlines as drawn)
GND on Bottom Layer (solid): 1700,5412.94 4855,5412.94 4950,5317.94 4950,1757.94 4855,1662.94 1705,1662.94 1605,1762.94 1605,5317.94 1700,5412.94
GND on Top Layer (solid): 1700,5412.94 4855,5412.94 4950,5317.94 4950,1757.94 4855,1662.94 1705,1662.94 1605,1762.94 1605,5317.94 1700,5412.94

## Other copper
Top Layer:
  region net +5V: 3940,4607.94 3920,4587.94 3940,4567.94
  region net 3V3: 2360,4607.94 2340,4587.94 2360,4567.94
  pour cut-out net S$53996: 4985,4892.94 4913.79,4821.73 4865.9,4821.73 4830,4785.83 4830,4647.94 4865,4612.94 4915,4612.94 4985,4542.94 5010,4542.94 5010,4567.94 5010,4892.94
  pour cut-out net S$53996: 4985,3514.99 4913.79,3443.78 4865.9,3443.78 4830,3407.88 4830,3269.99 4865,3234.99 4915,3234.99 4985,3164.99 5010,3164.99 5010,3189.99 5010,3514.99
  pour cut-out net S$53996: 4985,2137.04 4913.79,2065.83 4865.9,2065.83 4830,2029.93 4830,1892.04 4865,1857.04 4915,1857.04 4985,1787.04 5010,1787.04 5010,1812.04 5010,2137.04
  pour cut-out net S$53996: 1568.3,4548.14 1639.51,4619.35 1687.39,4619.35 1723.3,4655.25 1723.3,4793.14 1688.3,4828.14 1638.3,4828.14 1568.3,4898.14 1543.3,4898.14 1543.3,4873.14 1543.3,4548.14
  pour cut-out net S$53996: 1568.3,3170.19 1639.51,3241.4 1687.39,3241.4 1723.3,3277.3 1723.3,3415.19 1688.3,3450.19 1638.3,3450.19 1568.3,3520.19 1543.3,3520.19 1543.3,3495.19 1543.3,3170.19
  pour cut-out net S$53996: 1568.3,1792.24 1639.51,1863.45 1687.39,1863.45 1723.3,1899.35 1723.3,2037.24 1688.3,2072.24 1638.3,2072.24 1568.3,2142.24 1543.3,2142.24 1543.3,2117.24 1543.3,1792.24
  region net SW2_A: 4307.85,5257.62 4345.43,5295.19 4347.71,5262.4 4340.64,5255.33
  region net SW2_B: 4324.26,5060.51 4276.08,5082.95 4279.7,5053.91 4299.7,5044.59
  region net KEY18: 4857.53,5066.39 4857.48,5119.53 4832.7,5097.94 4832.71,5087.94
  region net OSCIN: 2747.82,4929.37 2785.36,4891.74 2783.46,4913.26 2769.34,4927.42
  region net OSCOUT: 2747.82,4666.51 2785.36,4704.13 2788.47,4677.62 2774.34,4663.46
  region net SWCLK: 4041.28,5240.88 4076.77,5276.38 4045.99,5278.72 4038.92,5271.65
  region net TX: 4041.28,5145.06 4076.79,5109.58 4046.01,5107.22 4038.94,5114.28
  region net SWDIO: 3941.28,5240.88 3976.77,5276.38 3945.99,5278.72 3938.92,5271.65
  region net RX: 3941.28,5145.07 3976.78,5109.58 3946.01,5107.22 3938.93,5114.29
  region net 3V3: 3863.84,5211.32 3844.62,5257.69 3828.45,5235.53 3836.74,5215.53
  region net GND: 2080.09,1647.75 2080.09,1712.25 2110.19,1690 2110.19,1670
  region net GND: 2830.09,1647.75 2830.09,1712.25 2860.19,1690 2860.19,1670
  region net GND: 2773.21,1647.75 2773.21,1712.25 2743.11,1690 2743.11,1670
  region net GND: 3580.09,1647.75 3580.09,1712.25 3610.19,1690 3610.19,1670
  region net GND: 3523.21,1647.75 3523.21,1712.25 3493.11,1690 3493.11,1670
  region net GND: 4273.21,1647.75 4273.21,1712.25 4243.11,1690 4243.11,1670
  region net KEY17: 1873.18,5047.58 1910.74,5009.98 1877.94,5007.71 1870.88,5014.79
  region net ANA1: 2158.53,4808.75 2111.29,4808.77 2124.9,4786.72 2144.9,4786.71
  region net 3V3: 2255.07,4852.39 2253.25,4805.18 2275.8,4817.94 2276.57,4837.94
  region net 3V3: 2502.23,5054.02 2454.99,5054.04 2468.6,5031.98 2488.6,5031.97
  region net U1_7: 2991.98,4747.19 2979.25,4759.92 2988.02,4763.03 2995.09,4755.96
  region net KEY6: 3230.75,4419.92 3218.02,4407.19 3214.91,4415.96 3221.98,4423.03
  region net KEY10: 3251,4380.88 3269,4380.88 3265,4389.28 3255,4389.28
  region net KEY15: 3281,4415.88 3299,4415.88 3295,4424.28 3285,4424.28
  region net KEY11: 3311,4380.88 3329,4380.88 3325,4389.28 3315,4389.28
  region net KEY7: 3341,4415.88 3359,4415.88 3355,4424.28 3345,4424.28
  region net KEY2: 3200.75,4384.92 3188.02,4372.19 3184.91,4380.96 3191.98,4388.03
  region net KEY14: 3161.98,4422.19 3149.25,4434.92 3158.02,4438.03 3165.09,4430.96
  region net KEY13: 3126.98,4452.19 3114.25,4464.92 3123.02,4468.03 3130.09,4460.96
  region net ANA1: 3085.86,4633.41 3068.88,4627.45 3069.35,4636.52 3079.82,4640.19
  region net ANA2: 3031,4610.88 3049,4610.88 3045,4619.28 3035,4619.28
  region net SWDIO: 3491.98,4928.69 3479.25,4915.96 3486.46,4914.4 3493.54,4921.48
  region net SWCLK: 3397.06,4943.94 3397.06,4961.94 3388.66,4957.94 3388.66,4947.94
  region net SWDIO: 3581.98,4947.19 3569.25,4959.92 3578.02,4963.03 3585.09,4955.96
  region net SWCLK: 3581.98,4997.19 3569.25,5009.92 3578.02,5013.03 3585.09,5005.96
  region net EC2: 3382.06,4993.94 3382.06,5011.94 3373.66,5007.94 3373.66,4997.94
  region net EC1: 3352.06,5018.94 3352.06,5036.94 3343.66,5032.94 3343.66,5022.94
  region net EC2: 3621.98,5077.19 3609.25,5089.92 3618.02,5093.03 3625.09,5085.96
  region net EC1: 3576.98,5072.19 3564.25,5084.92 3573.02,5088.03 3580.09,5080.96
  region net KEY18: 3330.75,5040.96 3318.02,5053.69 3314.91,5044.92 3321.98,5037.85
  region net KEY18: 3571.53,5109.61 3561.86,5124.8 3571.03,5126.04 3576.53,5117.4
  region net U1_7: 2845.75,4590.96 2833.02,4603.69 2829.91,4594.92 2836.98,4587.85
  region net KEY1: 3163.14,4804.8 3178.33,4814.47 3170.54,4819.47 3161.9,4813.97
  region net KEY5: 3201,4770.88 3219,4770.88 3215,4779.28 3205,4779.28
  region net KEY9: 3245.75,4829.92 3233.02,4817.19 3229.91,4825.96 3236.98,4833.03
  region net KEY16: 3660.75,4639.92 3648.02,4627.19 3644.91,4635.96 3651.98,4643.03
  region net KEY12: 3695.75,4669.92 3683.02,4657.19 3679.91,4665.96 3686.98,4673.03
  region net KEY8: 3730.75,4699.92 3718.02,4687.19 3714.91,4695.96 3721.98,4703.03
  region net KEY4: 3765.75,4729.92 3753.02,4717.19 3749.91,4725.96 3756.98,4733.03
  region net LEDG: 3326.67,4889.47 3341.86,4879.8 3343.1,4888.97 3334.46,4894.47
  region net LEDR: 3375.75,4894.92 3363.02,4882.19 3361.66,4889.2 3368.74,4896.28
  region net 3V3: 3433.22,4908.04 3450.67,4912.45 3449,4903.36 3439,4900.84
  region net 3V3: 3451.98,4917.17 3437.74,4906.15 3445,4901.15 3455,4908.89
  region net 3V3: 3451.98,4918.71 3437.74,4929.73 3445,4934.73 3455,4926.99
  region net 3V3: 3431,4925.88 3449,4925.88 3450,4934.28 3430,4934.28
  region net KEY3: 3291,4750.88 3309,4750.88 3305,4759.28 3295,4759.28
  region net GATE: 3371,4380.88 3389,4380.88 3385,4389.28 3375,4389.28
  region net GATE: 3380.75,4075.96 3368.02,4088.69 3364.91,4079.92 3371.98,4072.85
  region net LEDB: 3360.75,4544.92 3348.02,4532.19 3344.91,4540.96 3351.98,4548.03
  region net LEDB: 3691.98,4782.19 3679.25,4794.92 3688.02,4798.03 3695.09,4790.96
  region net LEDR: 3641.98,4827.19 3629.25,4839.92 3638.02,4843.03 3645.09,4835.96
  region net LEDG: 3646.98,4782.19 3634.25,4794.92 3643.02,4798.03 3650.09,4790.96
  region net 3V3: 3781,5110.88 3799,5110.88 3800,5119.28 3780,5119.28
  region net 3V3: 3118.95,4938.94 3118.95,4956.94 3127.35,4952.94 3127.35,4942.94
  region net 3V3: 3103.07,4938.94 3103.07,4956.94 3094.67,4952.94 3094.67,4942.94
  region net 3V3: 3531,4575 3549,4575 3545,4566.6 3535,4566.6
  region net 3V3: 3540.75,4594.92 3528.02,4582.19 3524.91,4590.96 3531.98,4598.03
  region net +5V: 3521,5170.88 3539,5170.88 3540,5179.28 3520,5179.28
  region net +5V: 3936,4660 3954,4660 3955,4651.6 3935,4651.6
  region net +5V: 3145.75,5109.92 3133.02,5097.19 3126.38,5102.42 3140.52,5116.56
  region net +5V: 3156.98,5097.19 3144.25,5109.92 3149.48,5116.56 3163.62,5102.42
  region net 3V3: 2356,4645 2374,4645 2375,4636.6 2355,4636.6
  region net 3V3: 3271.98,5062.19 3259.25,5074.92 3268.02,5078.03 3275.09,5070.96
  region net +5V: 3132.18,5123.7 3119.24,5110.76 3124.68,5104.12 3138.82,5118.26
  region net +5V: 3128.07,5113.79 3128.07,5132.09 3135,5132.94 3135,5112.94
  region net +5V: 3128.07,5113.79 3128.07,5132.09 3136.62,5132.94 3136.62,5112.94
  region net +5V: 2993.07,5278.79 2993.07,5297.09 3001.62,5297.94 3001.62,5277.94
  region net +5V: 2976.93,5278.79 2976.93,5297.09 2971.84,5297.94 2971.84,5277.94
  region net +5V: 2980.61,5276.55 2974.25,5293.72 2965.59,5292.48 2973.24,5271.85
  region net +5V: 3006.93,5278.79 3006.93,5297.09 2998.38,5297.94 2998.38,5277.94
  region net +5V: 3005.85,5296.01 3024.15,5296.01 3025,5304.56 3005,5304.56
  region net ANA2: 2458.07,4673.79 2458.07,4692.09 2466.62,4692.94 2466.62,4672.94
  region net 3V3: 2680.85,5236.01 2699.15,5236.01 2700,5244.56 2680,5244.56
  region net 3V3: 2680.85,5219.87 2699.15,5219.87 2700,5211.32 2680,5211.32
  region net 3V3: 2680.85,5191.31 2699.15,5191.31 2700,5199.86 2680,5199.86
  region net USB1_A5: 3151.75,5313.47 3172.01,5298.82 3177.69,5313.22 3169.48,5319.16
  region net USB1_B5: 3300.53,5139.95 3300.53,5115.97 3315.53,5136.4 3315.53,5150.54
  region net BUZZER1_2: 4472.12,4592.09 4450.23,4631.46 4436.15,4597.03 4448.27,4580.87
  region net BUZZER1_2: 4479.77,4631.46 4479.77,4592.09 4493.8,4601.74 4493.8,4621.74
  region net +5V: 4450.23,4718.38 4450.23,4684.42 4449.8,4719.68 4450.23,4718.38
  region net +5V: 4450.23,4723.79 4456.87,4698.47 4450.23,4718.38 4450.23,4723.79
  region net +5V: 4450.23,4723.79 4479.77,4719.12 4504.06,4745.66 4479.63,4749.52
  region net +5V: 4450.23,4684.42 4450.23,4723.79 4420.23,4715.54 4420.23,4695.54
  region net GATE: 3262.99,3976.72 3262.99,3998.43 3247.99,3978 3247.99,3963.86
  region net GATE: 3289.07,4008.47 3297.01,3984.76 3305.57,4006.44 3302.02,4017.03
  region net +5V: 3262.99,3917.41 3297.01,3917.41 3290,3887.41 3270,3887.41
  region net 3V3: 2442.99,4517.41 2442.99,4549.16 2412.99,4543.24 2412.99,4523.24
  region net U1_7: 2477.01,4576.72 2477.01,4608.47 2507.01,4602.64 2507.01,4582.64
  region net 3V3: 3357.99,5065.78 3357.99,5090.78 3342.99,5083.28 3342.99,5073.28
  region net USBDP: 3371.57,5153.47 3392.01,5139.07 3397.73,5153.39 3389.44,5159.23
  region net 3V3: 3007.71,4932.84 3007.71,4907.84 3022.4,4915.34 3022.4,4925.34
  region net 3V3: 2997.71,4628.15 2997.71,4603.15 3012.71,4623.58 3012.71,4637.73
  region net 3V3: 3527.5,4555.66 3548.31,4555.66 3545,4570.66 3535,4570.66
  region net +5V: 2962.71,5319.63 2927.29,5319.63 2940,5289.63 2960,5289.63
  region net +5V: 2962.71,5319.63 2927.29,5319.63 2914.93,5305.01 2936.14,5297.94
  region net +5V: 2927.29,5251.25 2962.71,5251.25 2960,5281.25 2940,5281.25
  region net OSCIN: 2882.29,4904.63 2882.29,4936.13 2852.29,4930.34 2852.29,4910.34
  region net OSCIN: 2912.5,4904.63 2887.5,4904.63 2895,4889.63 2905,4889.63
  region net OSCOUT: 2882.29,4654.75 2882.29,4686.25 2852.29,4680.54 2852.29,4660.54
  region net OSCOUT: 2887.5,4686.25 2912.5,4686.25 2905,4701.25 2895,4701.25
  region net U1_7: 2557.29,4574.75 2557.29,4606.25 2527.29,4602.64 2527.29,4582.64
  region net U1_7: 2592.71,4599.55 2589.56,4574.75 2603.15,4562.72 2604.75,4575.27
  region net ANA1: 2098.16,4720.66 2128.31,4685.22 2140.68,4716.97 2127.68,4732.26
  region net ANA2: 2466.69,4665.22 2466.69,4700.66 2450,4692.94 2450,4672.94
  region net +5V: 4342.29,4689.75 4342.29,4721.25 4312.29,4715.54 4312.29,4695.54
  region net +5V: 4377.71,4721.25 4377.71,4689.75 4407.71,4695.54 4407.71,4715.54
  region net +5V: 4377.71,4721.25 4377.71,4689.75 4407.71,4695.54 4407.71,4715.54
  region net R2_2: 2815.53,3769.95 2815.53,3735.93 2845.53,3742.94 2845.53,3762.94
  region net LED2_2: 2724.47,3735.93 2756.22,3769.95 2725.93,3781.46 2712.27,3766.83
  region net R2_2: 3739.47,3735.93 3739.47,3769.95 3709.47,3762.94 3709.47,3742.94
  region net LED3_2: 3798.78,3769.95 3830.53,3735.93 3842.73,3766.83 3829.07,3781.46
  region net R2_2: 3259.99,3273.47 3294.01,3273.47 3292,3318.47 3262,3318.47
  region net R2_2: 3259.99,3241.72 3259.99,3273.47 3229.99,3267.64 3229.99,3247.64
  region net R2_2: 3294.01,3273.47 3294.01,3241.72 3324.01,3247.64 3324.01,3267.64
  region net LED4_2: 3259.99,3182.41 3294.01,3182.41 3287,3152.41 3267,3152.41
  region net R2_2: 2508.99,2533.47 2543.01,2533.47 2536,2563.47 2516,2563.47
  region net LED5_2: 2508.99,2442.41 2543.01,2442.41 2536,2412.41 2516,2412.41
  region net R2_2: 4008.99,2533.47 4043.01,2533.47 4036,2563.47 4016,2563.47
  region net LED6_2: 4008.99,2442.41 4043.01,2442.41 4036,2412.41 4016,2412.41
  region net +5V: 3048.39,5374.82 3048.39,5406.57 3047.8,5400.74 3047.8,5380.74
  region net LED7_2: 3052.9,5315.51 3077.9,5315.51 3070.4,5300.51 3060.4,5300.51
  region net LED1_1: 3870.53,4992.24 3870.53,4970.93 3885.53,4974.74 3885.53,4984.74
  region net LEDR: 3780.57,4970.93 3779.47,4995.91 3765.57,4970.58 3766.16,4957.03
  region net LED1_3: 3870.53,4901.14 3855.82,4880.93 3870.23,4875.25 3876.19,4883.43
  region net LEDG: 3779.47,4910.44 3779.47,4885.44 3764.47,4892.94 3764.47,4902.94
  region net LED1_4: 3855.99,4824.95 3870.53,4804.61 3875.85,4822.02 3869.36,4829.68
  region net LEDB: 3779.47,4820.44 3779.47,4795.44 3764.47,4802.94 3764.47,4812.94
  region net EC2: 4246.22,4955.93 4214.47,4955.93 4220.3,4925.93 4240.3,4925.93
  region net EC2: 4217.8,4989.95 4242.8,4989.95 4235.3,5004.95 4225.3,5004.95
  region net SW2_B: 4305.53,4989.95 4273.78,4989.95 4279.7,5019.95 4299.7,5019.95
  region net BUZZ: 4127.01,4640.44 4127.01,4615.44 4142.01,4622.94 4142.01,4632.94
  region net BUZZ: 4127.01,4637.84 4127.01,4612.84 4142.01,4620.34 4142.01,4630.34
  region net BUZZ: 4092.99,4615.74 4092.99,4640.74 4077.99,4633.24 4077.99,4623.24
  region net BUZZ: 4190.32,4615.44 4190.32,4637.15 4175.32,4632.94 4175.32,4622.94
  region net BUZZ: 4190.32,4613.53 4190.32,4637.15 4175.32,4630.34 4175.32,4620.34
  region net BUZZER1_2: 4329.68,4599.75 4329.68,4576.13 4359.68,4577.94 4359.68,4597.94
  region net BUZZER1_2: 4329.68,4599.75 4329.68,4576.13 4359.68,4577.94 4359.68,4597.94
  region net GATE: 3303.09,3727.35 3328.09,3727.35 3307.66,3742.35 3293.52,3742.35
  region net +5V: 3302.56,3791.85 3344.69,3802.15 3304.8,3823.28 3282.07,3817.73
  region net +5V: 3344.69,3802.15 3344.69,3778.53 3374.69,3780.34 3374.69,3800.34
  region net R2_2: 3247.45,3741.13 3205.32,3741.13 3211.4,3706.54 3241.4,3706.54
  region net R2_2: 3205.32,3741.13 3205.32,3764.75 3175.32,3762.94 3175.32,3742.94
  region net +5V: 4551.42,4791.4 4551.42,4832.16 4521.42,4791.3 4521.42,4763.01
  region net BUZZER1_2: 4551.42,4653.61 4551.42,4694.36 4521.42,4653.5 4521.42,4625.21
  region net BUZZER1_2: 4551.42,4653.61 4551.42,4694.36 4521.42,4653.5 4521.42,4625.22
  region net LED2_2: 2550.6,3815.93 2550.6,3776.56 2580.6,3786.24 2580.6,3806.24
  region net LED3_2: 4001.39,3776.56 4001.39,3815.93 3971.39,3806.24 3971.39,3786.24
  region net LED4_2: 3252.39,3065.93 3301.6,3065.93 3287,3095.93 3267,3095.93
  region net LED5_2: 2501.39,2315.93 2550.6,2315.93 2536,2345.93 2516,2345.93
  region net LED6_2: 4001.39,2315.93 4050.6,2315.93 4036,2345.93 4016,2345.93
  region net +5V: 3528.61,5244.54 3528.61,5269.54 3522.7,5262.04 3522.7,5252.04
  region net +5V: 3540.42,5234.42 3528.61,5234.42 3529.5,5222.44 3539.5,5222.44
  region net +5V: 3528.61,5269.54 3528.61,5244.54 3534.5,5252.04 3534.5,5262.04
  region net +5V: 3528.61,5234.42 3516.8,5234.42 3517.7,5220.24 3527.7,5220.24
  region net USB1_A5: 3477.43,5279.69 3489.24,5279.69 3488.34,5294.69 3478.34,5294.69
  region net USBDM: 3469.57,5234.42 3457.75,5234.42 3458.7,5219.42 3468.7,5219.42
  region net USBDP: 3438.07,5279.69 3449.87,5279.69 3449,5288.94 3439,5288.94
  region net USBDM: 3430.2,5234.42 3418.38,5234.42 3419.3,5219.42 3429.3,5219.42
  region net USBDP: 3410.5,5234.42 3398.7,5234.42 3399.6,5219.42 3409.6,5219.42
  region net USBDP: 3398.7,5279.69 3410.5,5279.69 3409.6,5287.54 3399.6,5287.54
  region net USB1_B5: 3371.13,5234.42 3359.33,5234.42 3360.2,5219.42 3370.2,5219.42
  region net +5V: 3339.64,5244.54 3339.64,5269.54 3333.7,5262.04 3333.7,5252.04
  region net +5V: 3351.46,5234.42 3339.64,5234.42 3340.6,5219.42 3350.6,5219.42
  region net +5V: 3339.63,5269.54 3339.63,5244.54 3345.6,5252.04 3345.6,5262.04
  region net +5V: 3339.63,5234.42 3327.82,5234.42 3328.7,5219.42 3338.7,5219.42
  region net LED7_2: 3052.9,5229.08 3077.9,5229.08 3070.4,5244.08 3060.4,5244.08
  region net LED: 3090,5107.45 3065.38,5103.09 3089.03,5092.04 3101.04,5094.17
  region net EC1: 4293.31,4795.66 4293.31,4760.22 4323.31,4767.94 4323.31,4787.94
  region net SW2_A: 4367.5,4888.47 4392.5,4888.47 4385,4903.47 4375,4903.47
  region net EC1: 4397.01,4797.41 4362.99,4829.16 4351.48,4798.86 4366.11,4785.21
  region net EC1: 4390.87,4829.16 4397.01,4804.93 4406.73,4827.6 4403.88,4838.89
  region net 3V3: 2736.03,5246.76 2736.03,5274.32 2706.03,5270.54 2706.03,5250.54
  region net +5V: 2863.97,5311.72 2863.97,5284.16 2893.97,5287.94 2893.97,5307.94
  region net 3V3: 3462.5,4979.63 3437.5,4979.63 3445,4964.63 3455,4964.63
  region net KEY9: 3133.62,4873.54 3133.57,4862.91 3148.57,4863.14 3148.62,4873.14
  region net KEY5: 3133.63,4853.86 3133.56,4843.23 3148.56,4843.44 3148.63,4853.44
  region net KEY1: 3133.6,4834.17 3133.59,4823.54 3148.59,4823.84 3148.6,4833.84
  region net OSCIN: 3085.18,4803.86 3085.16,4814.49 3070.16,4814.14 3070.18,4804.14
  region net OSCOUT: 3085.18,4784.17 3085.15,4794.8 3070.15,4794.44 3070.18,4784.44
  region net U1_7: 3085.19,4764.49 3085.14,4775.12 3070.15,4774.74 3070.19,4764.74
  region net 3V3: 3085.2,4725.12 3085.13,4735.75 3070.14,4735.34 3070.2,4725.34
  region net 3V3: 3133.63,4735.75 3133.56,4725.12 3148.56,4725.34 3148.62,4735.34
  region net ANA2: 3085.17,4705.43 3085.17,4716.06 3070.17,4715.74 3070.17,4705.74
  region net ANA1: 3085.17,4685.75 3085.16,4696.38 3070.16,4696.04 3070.17,4686.04
  region net KEY13: 3127.09,4666.06 3102.09,4666.06 3122.52,4651.06 3136.66,4651.06
  region net KEY14: 3173.74,4588.1 3163.11,4588.12 3163.4,4573.12 3173.4,4573.1
  region net KEY2: 3193.44,4588.1 3182.81,4588.11 3183.1,4573.11 3193.1,4573.1
  region net KEY6: 3213.11,4588.07 3202.48,4588.14 3202.7,4573.14 3212.7,4573.07
  region net KEY10: 3232.81,4588.07 3222.18,4588.14 3222.4,4573.14 3232.4,4573.08
  region net KEY15: 3252.48,4588.08 3241.85,4588.13 3242.1,4573.13 3252.1,4573.08
  region net KEY11: 3272.18,4588.09 3261.55,4588.13 3261.8,4573.13 3271.8,4573.09
  region net KEY7: 3291.85,4588.09 3281.22,4588.12 3281.5,4573.12 3291.5,4573.09
  region net GATE: 3331.22,4588.1 3320.59,4588.11 3320.9,4573.11 3330.9,4573.1
  region net LEDB: 3350.92,4588.11 3340.29,4588.11 3340.6,4573.11 3350.6,4573.11
  region net 3V3: 3390.29,4624.74 3390.29,4599.74 3405.29,4607.24 3405.29,4617.24
  region net KEY16: 3468.24,4676.69 3468.22,4666.06 3483.22,4666.34 3483.24,4676.34
  region net KEY12: 3468.24,4696.38 3468.23,4685.75 3483.23,4686.04 3483.24,4696.04
  region net KEY8: 3468.27,4716.06 3468.2,4705.43 3483.2,4705.64 3483.27,4715.64
  region net KEY4: 3468.26,4735.75 3468.2,4725.12 3483.2,4725.34 3483.26,4735.34
  region net BUZZ: 3468.26,4755.43 3468.21,4744.8 3483.21,4745.04 3483.26,4755.04
  region net TX: 3468.25,4775.12 3468.21,4764.49 3483.21,4764.74 3483.25,4774.74
  region net RX: 3468.25,4794.8 3468.22,4784.17 3483.22,4784.44 3483.25,4794.44
  region net USBDM: 3468.24,4814.49 3468.22,4803.86 3483.22,4804.14 3483.24,4814.14
  region net USBDP: 3468.24,4834.17 3468.23,4823.54 3483.23,4823.84 3483.24,4833.84
  region net SWDIO: 3468.23,4843.23 3468.23,4853.86 3483.1,4853.54 3483.1,4843.54
  region net 3V3: 3431.5,4893.23 3456.5,4893.23 3449,4908.23 3439,4908.23
  region net 3V3: 3453.53,4890.35 3444.92,4893.23 3436.84,4893.23 3442.93,4893.89 3444.92,4893.23 3461.84,4893.23 3453.53,4890.35
  region net SWCLK: 3390.29,4965.44 3390.29,4940.44 3405,4947.94 3405,4957.94
  region net LEDR: 3370.59,4922.72 3359.96,4922.77 3360.2,4907.77 3370.2,4907.72
  region net LEDG: 3350.92,4922.75 3340.29,4922.75 3340.6,4907.75 3350.6,4907.75
  region net EC2: 3331.22,4971.18 3320.59,4971.17 3320.9,4983.84 3330.9,4983.84
  region net EC1: 3311.55,4971.18 3300.92,4971.16 3301.2,4986.16 3311.2,4986.18
  region net KEY18: 3291.85,4971.19 3281.22,4971.16 3281.5,4986.16 3291.5,4986.19
  region net KEY3: 3272.18,4922.73 3261.55,4922.77 3261.8,4907.77 3271.8,4907.73
  region net LED: 3232.81,4971.2 3222.18,4971.14 3222.4,4986.14 3232.4,4986.2
  region net KEY17: 3213.11,4971.21 3202.48,4971.14 3202.7,4986.14 3212.7,4986.2
  region net 3V3: 3163.11,4935.44 3163.11,4960.44 3148.11,4952.94 3148.11,4942.94
  region net 3V3: 3173.74,4922.74 3163.11,4922.76 3163.4,4909.55 3173.4,4909.53
  region net LED1_1: 4017,4994.49 4016.96,4964.96 4003.19,4974.74 4003.21,4984.74
  region net +5V: 4043.03,4913.77 4043.01,4943.3 4056.8,4938.54 4056.8,4918.54
  region net LED1_3: 4016.99,4862.58 4016.97,4892.11 4003.2,4882.34 4003.2,4872.34
  region net LED1_4: 4017,4811.39 4016.96,4840.92 4003.19,4831.14 4003.21,4821.14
